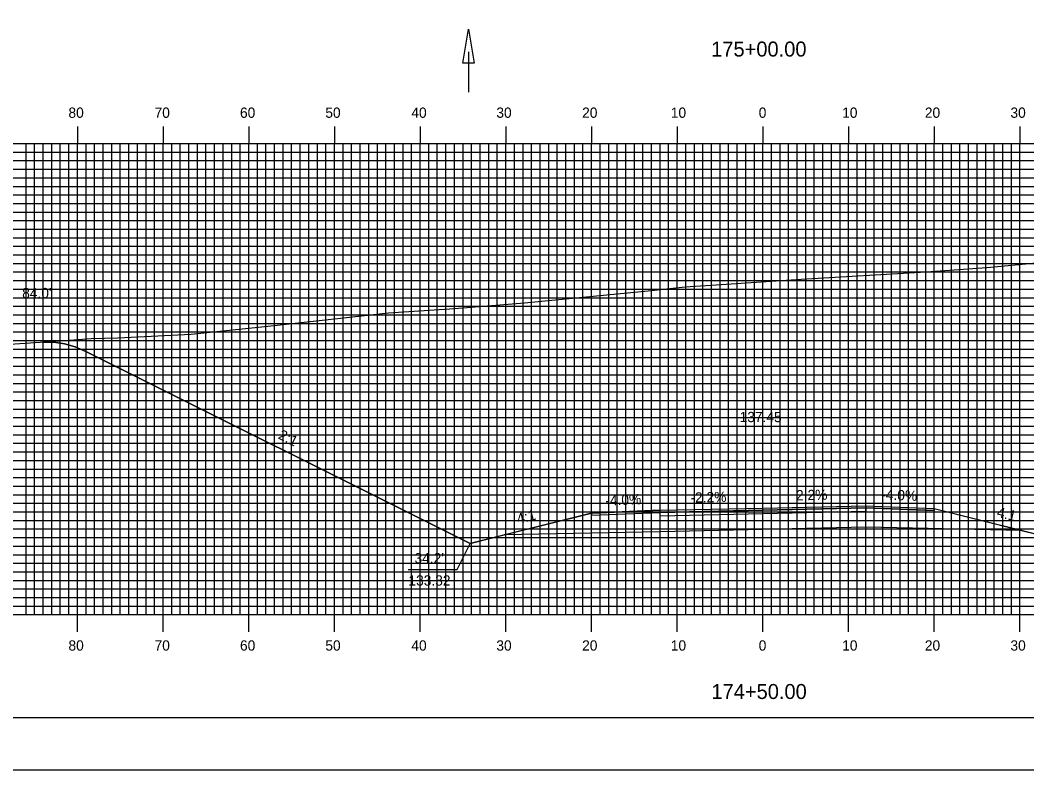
# Model space of a CAD drawing. Extents: x 1783828 to 1784171, y 442591 to 442811.
# Drawn here: x 1783906.8 to 1784024.3, y 442590.5 to 442678.1 of the extents above; entities that cross this region are included whole.
import ezdxf

# ---------------------------------------------------------------- set-up
doc = ezdxf.new("R2010")
doc.units = 0
for name, color, linetype in [('ANNOTATION', 7, 'Continuous'), ('BORDER', 7, 'Continuous'), ('D_Drainage_Ditch_Line', 7, 'Continuous'), ('D_Roadway_Centerline', 7, 'Continuous'), ('D_Roadway_Centerline_Text', 7, 'Continuous'), ('D_Roadway_Edge_Shoulder', 7, 'Continuous'), ('D_Roadway_Edge_TW', 7, 'Continuous'), ('D_Roadway_Pavement', 7, 'Continuous'), ('D_Roadway_SlopeLines', 7, 'Continuous'), ('D_Roadway_SubGrade', 7, 'Continuous'), ('D_Text_Standard', 7, 'Continuous'), ('H_V ANNOTATION', 7, 'Continuous'), ('MAJOR', 7, 'Continuous'), ('MINOR', 7, 'Continuous'), ('PLOT BOUNDARY', 7, 'Continuous'), ('S_Roadway_Centerline', 7, 'Continuous')]:
    doc.layers.add(name, color=color, linetype=linetype)

msp = doc.modelspace()

# ---------------------------------------------------------------- linework, layer by layer
at = {"layer": 'ANNOTATION'}
msp.add_lwpolyline([(1783952.09, 442613.93), (1783957.79, 442613.93), (1783959.31, 442616.98)], dxfattribs=at)
at = {"layer": 'BORDER'}
msp.add_lwpolyline([(1783843.89, 442596.67), (1784163.89, 442596.67), (1784163.89, 442806.67), (1783843.89, 442806.67)], close=True, dxfattribs=at)
at = {"layer": 'D_Drainage_Ditch_Line'}
msp.add_line((1783959.12, 442674.38), (1783959.12, 442669.68), dxfattribs=at)
msp.add_lwpolyline([(1783959.78, 442673.06), (1783958.47, 442673.06), (1783959.12, 442677)], close=True, dxfattribs=at)
at = {"layer": 'D_Roadway_Centerline'}
msp.add_lwpolyline([(1783909.48, 442640.49), (1783910.73, 442640.48), (1783911.98, 442640.3), (1783913.23, 442639.94), (1783914.48, 442639.4), (1783959.31, 442616.98), (1783963.31, 442617.98), (1783973.49, 442620.53), (1783981.49, 442620.85), (1783993.49, 442621.11), (1784005.49, 442621.38), (1784013.49, 442621.06), (1784023.66, 442618.51), (1784028.93, 442617.2), (1784105.33, 442655.4), (1784106.58, 442655.96), (1784107.83, 442656.39), (1784109.08, 442656.7), (1784110.33, 442656.87)], dxfattribs=at)
at = {"layer": 'D_Roadway_Edge_Shoulder'}
for points in [[(1783981.49, 442620.85), (1783973.49, 442620.53), (1783973.49, 442620.28), (1783981.49, 442620.6)], [(1784005.49, 442621.38), (1784013.49, 442621.06), (1784013.49, 442620.81), (1784005.49, 442621.13)]]:
    msp.add_lwpolyline(points, close=True, dxfattribs=at)
at = {"layer": 'D_Roadway_Edge_TW'}
msp.add_lwpolyline([(1783981.49, 442620.6), (1783981.49, 442620.85), (1783993.49, 442621.11), (1784005.49, 442621.38), (1784005.49, 442621.13), (1783993.49, 442620.86)], close=True, dxfattribs=at)
at = {"layer": 'D_Roadway_Pavement'}
msp.add_lwpolyline([(1783981.49, 442620.18), (1783981.49, 442620.6), (1783993.49, 442620.86), (1784005.49, 442621.13), (1784005.49, 442620.71), (1783993.49, 442620.44)], close=True, dxfattribs=at)
at = {"layer": 'D_Roadway_SlopeLines'}
for points in [[(1783959.31, 442616.98), (1783914.48, 442639.4), (1783913.23, 442639.94), (1783911.98, 442640.3), (1783910.73, 442640.48), (1783909.48, 442640.49)], [(1783973.49, 442620.53), (1783959.31, 442616.98)], [(1784013.49, 442621.06), (1784028.93, 442617.2)]]:
    msp.add_lwpolyline(points, dxfattribs=at)
at = {"layer": 'D_Roadway_SubGrade'}
msp.add_lwpolyline([(1783981.49, 442618.35), (1783963.31, 442617.98), (1783973.49, 442620.53), (1783973.49, 442620.28), (1783981.49, 442620.6), (1783993.49, 442620.86), (1784005.49, 442621.13), (1784013.49, 442620.81), (1784013.49, 442621.06), (1784023.66, 442618.51), (1784005.49, 442618.88), (1783993.49, 442618.61)], close=True, dxfattribs=at)
at = {"layer": 'MAJOR'}
for p, q in [((1783913.49, 442665.67), (1783913.49, 442663.67)), ((1783923.49, 442665.67), (1783923.49, 442663.67)), ((1783933.49, 442665.67), (1783933.49, 442663.67)), ((1783943.49, 442665.67), (1783943.49, 442663.67)), ((1783953.49, 442665.67), (1783953.49, 442663.67)), ((1783963.49, 442665.67), (1783963.49, 442663.67)), ((1783973.49, 442665.67), (1783973.49, 442663.67)), ((1783983.49, 442665.67), (1783983.49, 442663.67)), ((1783993.49, 442665.67), (1783993.49, 442663.67)), ((1784003.49, 442665.67), (1784003.49, 442663.67)), ((1784013.49, 442665.67), (1784013.49, 442663.67)), ((1784023.49, 442665.67), (1784023.49, 442663.67)), ((1783853.49, 442663.67), (1784133.49, 442663.67)), ((1783853.49, 442663.67), (1784133.49, 442663.67)), ((1783913.49, 442608.67), (1783913.49, 442663.67)), ((1783923.49, 442608.67), (1783923.49, 442663.67)), ((1783933.49, 442608.67), (1783933.49, 442663.67)), ((1783943.49, 442608.67), (1783943.49, 442663.67)), ((1783953.49, 442608.67), (1783953.49, 442663.67)), ((1783963.49, 442608.67), (1783963.49, 442663.67)), ((1783973.49, 442608.67), (1783973.49, 442663.67)), ((1783983.49, 442608.67), (1783983.49, 442663.67)), ((1783993.49, 442608.67), (1783993.49, 442663.67)), ((1784003.49, 442608.67), (1784003.49, 442663.67)), ((1784013.49, 442608.67), (1784013.49, 442663.67)), ((1784023.49, 442608.67), (1784023.49, 442663.67)), ((1783853.49, 442658.67), (1784133.49, 442658.67)), ((1783853.49, 442653.67), (1784133.49, 442653.67)), ((1783853.49, 442648.67), (1784133.49, 442648.67)), ((1783853.49, 442643.67), (1784133.49, 442643.67)), ((1783853.49, 442638.67), (1784133.49, 442638.67)), ((1783853.49, 442633.67), (1784133.49, 442633.67)), ((1783853.49, 442628.67), (1784133.49, 442628.67)), ((1783853.49, 442623.67), (1784133.49, 442623.67)), ((1783853.49, 442618.67), (1784133.49, 442618.67)), ((1783853.49, 442613.67), (1784133.49, 442613.67)), ((1783853.49, 442608.67), (1784133.49, 442608.67)), ((1783853.49, 442608.67), (1784133.49, 442608.67)), ((1783913.49, 442606.66), (1783913.49, 442608.67)), ((1783923.49, 442606.66), (1783923.49, 442608.67)), ((1783933.49, 442606.66), (1783933.49, 442608.67)), ((1783943.49, 442606.66), (1783943.49, 442608.67)), ((1783953.49, 442606.66), (1783953.49, 442608.67)), ((1783963.49, 442606.66), (1783963.49, 442608.67)), ((1783973.49, 442606.66), (1783973.49, 442608.67)), ((1783983.49, 442606.66), (1783983.49, 442608.67)), ((1783993.49, 442606.66), (1783993.49, 442608.67)), ((1784003.49, 442606.66), (1784003.49, 442608.67)), ((1784013.49, 442606.66), (1784013.49, 442608.67)), ((1784023.49, 442606.66), (1784023.49, 442608.67))]:
    msp.add_line(p, q, dxfattribs=at)
at = {"layer": 'MINOR'}
for p, q in [((1783853.49, 442662.67), (1784133.49, 442662.67)), ((1783907.49, 442608.67), (1783907.49, 442663.67)), ((1783908.49, 442608.67), (1783908.49, 442663.67)), ((1783909.49, 442608.67), (1783909.49, 442663.67)), ((1783910.49, 442608.67), (1783910.49, 442663.67)), ((1783911.49, 442608.67), (1783911.49, 442663.67)), ((1783912.49, 442608.67), (1783912.49, 442663.67)), ((1783914.49, 442608.67), (1783914.49, 442663.67)), ((1783915.49, 442608.67), (1783915.49, 442663.67)), ((1783916.49, 442608.67), (1783916.49, 442663.67)), ((1783917.49, 442608.67), (1783917.49, 442663.67)), ((1783918.49, 442608.67), (1783918.49, 442663.67)), ((1783919.49, 442608.67), (1783919.49, 442663.67)), ((1783920.49, 442608.67), (1783920.49, 442663.67)), ((1783921.49, 442608.67), (1783921.49, 442663.67)), ((1783922.49, 442608.67), (1783922.49, 442663.67)), ((1783924.49, 442608.67), (1783924.49, 442663.67)), ((1783925.49, 442608.67), (1783925.49, 442663.67)), ((1783926.49, 442608.67), (1783926.49, 442663.67)), ((1783927.49, 442608.67), (1783927.49, 442663.67)), ((1783928.49, 442608.67), (1783928.49, 442663.67)), ((1783929.49, 442608.67), (1783929.49, 442663.67)), ((1783930.49, 442608.67), (1783930.49, 442663.67)), ((1783931.49, 442608.67), (1783931.49, 442663.67)), ((1783932.49, 442608.67), (1783932.49, 442663.67)), ((1783934.49, 442608.67), (1783934.49, 442663.67)), ((1783935.49, 442608.67), (1783935.49, 442663.67)), ((1783936.49, 442608.67), (1783936.49, 442663.67)), ((1783937.49, 442608.67), (1783937.49, 442663.67)), ((1783938.49, 442608.67), (1783938.49, 442663.67)), ((1783939.49, 442608.67), (1783939.49, 442663.67)), ((1783940.49, 442608.67), (1783940.49, 442663.67)), ((1783941.49, 442608.67), (1783941.49, 442663.67)), ((1783942.49, 442608.67), (1783942.49, 442663.67)), ((1783944.49, 442608.67), (1783944.49, 442663.67)), ((1783945.49, 442608.67), (1783945.49, 442663.67)), ((1783946.49, 442608.67), (1783946.49, 442663.67)), ((1783947.49, 442608.67), (1783947.49, 442663.67)), ((1783948.49, 442608.67), (1783948.49, 442663.67)), ((1783949.49, 442608.67), (1783949.49, 442663.67)), ((1783950.49, 442608.67), (1783950.49, 442663.67)), ((1783951.49, 442608.67), (1783951.49, 442663.67)), ((1783952.49, 442608.67), (1783952.49, 442663.67)), ((1783954.49, 442608.67), (1783954.49, 442663.67)), ((1783955.49, 442608.67), (1783955.49, 442663.67)), ((1783956.49, 442608.67), (1783956.49, 442663.67)), ((1783957.49, 442608.67), (1783957.49, 442663.67)), ((1783958.49, 442608.67), (1783958.49, 442663.67)), ((1783959.49, 442608.67), (1783959.49, 442663.67)), ((1783960.49, 442608.67), (1783960.49, 442663.67)), ((1783961.49, 442608.67), (1783961.49, 442663.67)), ((1783962.49, 442608.67), (1783962.49, 442663.67)), ((1783964.49, 442608.67), (1783964.49, 442663.67)), ((1783965.49, 442608.67), (1783965.49, 442663.67)), ((1783966.49, 442608.67), (1783966.49, 442663.67)), ((1783967.49, 442608.67), (1783967.49, 442663.67)), ((1783968.49, 442608.67), (1783968.49, 442663.67)), ((1783969.49, 442608.67), (1783969.49, 442663.67)), ((1783970.49, 442608.67), (1783970.49, 442663.67)), ((1783971.49, 442608.67), (1783971.49, 442663.67)), ((1783972.49, 442608.67), (1783972.49, 442663.67)), ((1783974.49, 442608.67), (1783974.49, 442663.67)), ((1783975.49, 442608.67), (1783975.49, 442663.67)), ((1783976.49, 442608.67), (1783976.49, 442663.67)), ((1783977.49, 442608.67), (1783977.49, 442663.67)), ((1783978.49, 442608.67), (1783978.49, 442663.67)), ((1783979.49, 442608.67), (1783979.49, 442663.67)), ((1783980.49, 442608.67), (1783980.49, 442663.67)), ((1783981.49, 442608.67), (1783981.49, 442663.67)), ((1783982.49, 442608.67), (1783982.49, 442663.67)), ((1783984.49, 442608.67), (1783984.49, 442663.67)), ((1783985.49, 442608.67), (1783985.49, 442663.67)), ((1783986.49, 442608.67), (1783986.49, 442663.67)), ((1783987.49, 442608.67), (1783987.49, 442663.67)), ((1783988.49, 442608.67), (1783988.49, 442663.67)), ((1783989.49, 442608.67), (1783989.49, 442663.67)), ((1783990.49, 442608.67), (1783990.49, 442663.67)), ((1783991.49, 442608.67), (1783991.49, 442663.67)), ((1783992.49, 442608.67), (1783992.49, 442663.67)), ((1783994.49, 442608.67), (1783994.49, 442663.67)), ((1783995.49, 442608.67), (1783995.49, 442663.67)), ((1783996.49, 442608.67), (1783996.49, 442663.67)), ((1783997.49, 442608.67), (1783997.49, 442663.67)), ((1783998.49, 442608.67), (1783998.49, 442663.67)), ((1783999.49, 442608.67), (1783999.49, 442663.67)), ((1784000.49, 442608.67), (1784000.49, 442663.67)), ((1784001.49, 442608.67), (1784001.49, 442663.67)), ((1784002.49, 442608.67), (1784002.49, 442663.67)), ((1784004.49, 442608.67), (1784004.49, 442663.67)), ((1784005.49, 442608.67), (1784005.49, 442663.67)), ((1784006.49, 442608.67), (1784006.49, 442663.67)), ((1784007.49, 442608.67), (1784007.49, 442663.67)), ((1784008.49, 442608.67), (1784008.49, 442663.67)), ((1784009.49, 442608.67), (1784009.49, 442663.67)), ((1784010.49, 442608.67), (1784010.49, 442663.67)), ((1784011.49, 442608.67), (1784011.49, 442663.67)), ((1784012.49, 442608.67), (1784012.49, 442663.67)), ((1784014.49, 442608.67), (1784014.49, 442663.67)), ((1784015.49, 442608.67), (1784015.49, 442663.67)), ((1784016.49, 442608.67), (1784016.49, 442663.67)), ((1784017.49, 442608.67), (1784017.49, 442663.67)), ((1784018.49, 442608.67), (1784018.49, 442663.67)), ((1784019.49, 442608.67), (1784019.49, 442663.67)), ((1784020.49, 442608.67), (1784020.49, 442663.67)), ((1784021.49, 442608.67), (1784021.49, 442663.67)), ((1784022.49, 442608.67), (1784022.49, 442663.67)), ((1783853.49, 442661.67), (1784133.49, 442661.67)), ((1783853.49, 442660.67), (1784133.49, 442660.67)), ((1783853.49, 442659.67), (1784133.49, 442659.67)), ((1783853.49, 442657.67), (1784133.49, 442657.67)), ((1783853.49, 442656.67), (1784133.49, 442656.67)), ((1783853.49, 442655.67), (1784133.49, 442655.67)), ((1783853.49, 442654.67), (1784133.49, 442654.67)), ((1783853.49, 442652.67), (1784133.49, 442652.67)), ((1783853.49, 442651.67), (1784133.49, 442651.67)), ((1783853.49, 442650.67), (1784133.49, 442650.67)), ((1783853.49, 442649.67), (1784133.49, 442649.67)), ((1783853.49, 442647.67), (1784133.49, 442647.67)), ((1783853.49, 442646.67), (1784133.49, 442646.67)), ((1783853.49, 442645.67), (1784133.49, 442645.67)), ((1783853.49, 442644.67), (1784133.49, 442644.67)), ((1783853.49, 442642.67), (1784133.49, 442642.67)), ((1783853.49, 442641.67), (1784133.49, 442641.67)), ((1783853.49, 442640.67), (1784133.49, 442640.67)), ((1783853.49, 442639.67), (1784133.49, 442639.67)), ((1783853.49, 442637.67), (1784133.49, 442637.67)), ((1783853.49, 442636.67), (1784133.49, 442636.67)), ((1783853.49, 442635.67), (1784133.49, 442635.67)), ((1783853.49, 442634.67), (1784133.49, 442634.67)), ((1783853.49, 442632.67), (1784133.49, 442632.67)), ((1783853.49, 442631.67), (1784133.49, 442631.67)), ((1783853.49, 442630.67), (1784133.49, 442630.67)), ((1783853.49, 442629.67), (1784133.49, 442629.67)), ((1783853.49, 442627.67), (1784133.49, 442627.67)), ((1783853.49, 442626.67), (1784133.49, 442626.67)), ((1783853.49, 442625.67), (1784133.49, 442625.67)), ((1783853.49, 442624.67), (1784133.49, 442624.67)), ((1783853.49, 442622.67), (1784133.49, 442622.67)), ((1783853.49, 442621.67), (1784133.49, 442621.67)), ((1783853.49, 442620.67), (1784133.49, 442620.67)), ((1783853.49, 442619.67), (1784133.49, 442619.67)), ((1783853.49, 442617.67), (1784133.49, 442617.67)), ((1783853.49, 442616.67), (1784133.49, 442616.67)), ((1783853.49, 442615.67), (1784133.49, 442615.67)), ((1783853.49, 442614.67), (1784133.49, 442614.67)), ((1783853.49, 442612.67), (1784133.49, 442612.67)), ((1783853.49, 442611.67), (1784133.49, 442611.67)), ((1783853.49, 442610.67), (1784133.49, 442610.67)), ((1783853.49, 442609.67), (1784133.49, 442609.67))]:
    msp.add_line(p, q, dxfattribs=at)
at = {"layer": 'PLOT BOUNDARY'}
msp.add_lwpolyline([(1783827.7, 442590.55), (1784167.7, 442590.55), (1784167.7, 442810.55), (1783827.7, 442810.55)], close=True, dxfattribs=at)
at = {"layer": 'S_Roadway_Centerline'}
msp.add_lwpolyline([(1783853.49, 442636.66), (1783867.47, 442637.71), (1783867.88, 442637.74), (1783868.37, 442637.77), (1783880.33, 442638.35), (1783890.65, 442639.22), (1783893.25, 442639.41), (1783912.06, 442640.66), (1783915.08, 442640.9), (1783918.2, 442641), (1783926.75, 442641.42), (1783936.45, 442642.43), (1783949.8, 442643.89), (1783957.51, 442644.42), (1783965.65, 442645.08), (1783980.48, 442646.51), (1783984.4, 442646.92), (1783988.6, 442647.2), (1783997.96, 442647.84), (1784012.54, 442648.67), (1784019.62, 442649.19), (1784025.41, 442649.73)], dxfattribs=at)

# ---------------------------------------------------------------- texts
at = {"layer": 'ANNOTATION'}
for s, rotation, p in [('2:1', 333.4349, (1783936.83, 442629.26)), ('-4.0%', 2.2906, (1783975.12, 442621.39)), ('-2.2%', 1.2603, (1783985.05, 442621.73)), ('2.2%', 1.2603, (1783997.37, 442622)), ('-4.0%', 357.7094, (1784007.28, 442622.11)), ('4:1', 14.0362, (1783964.93, 442619.25)), ('4:1', 345.9638, (1784020.71, 442620.11))]:
    msp.add_text(s, height=1.2, rotation=rotation, dxfattribs=at).set_placement(p)
for s, p in [("34.2'", (1783952.83, 442614.66)), ('133.32', (1783952.12, 442612.06))]:
    msp.add_text(s, height=1.2, dxfattribs=at).set_placement(p)
at = {"layer": 'D_Roadway_Centerline'}
for s, p in [('C', (1783993.48, 442621.11)), ('L', (1783993.49, 442621.1))]:
    msp.add_text(s, height=0.0146, dxfattribs=at).set_placement(p)
at = {"layer": 'D_Roadway_Centerline_Text'}
msp.add_text('137.45', height=1.2, dxfattribs=at).set_placement((1783990.77, 442631.14))
at = {"layer": 'D_Text_Standard'}
msp.add_text("84.0'", height=1.2, dxfattribs=at).set_placement((1783907.04, 442645.61))
at = {"layer": 'H_V ANNOTATION'}
for s, height, p in [('175+00.00', 1.75, (1783987.45, 442673.82)), ('80', 1.2, (1783912.44, 442666.67)), ('70', 1.2, (1783922.49, 442666.67)), ('60', 1.2, (1783932.46, 442666.67)), ('50', 1.2, (1783942.42, 442666.67)), ('40', 1.2, (1783952.46, 442666.67)), ('30', 1.2, (1783962.38, 442666.67)), ('20', 1.2, (1783972.39, 442666.67)), ('10', 1.2, (1783982.74, 442666.67)), ('0', 1.2, (1783993, 442666.67)), ('10', 1.2, (1784002.74, 442666.67)), ('20', 1.2, (1784012.39, 442666.67)), ('30', 1.2, (1784022.38, 442666.67)), ('80', 1.2, (1783912.44, 442604.47)), ('70', 1.2, (1783922.49, 442604.47)), ('60', 1.2, (1783932.46, 442604.47)), ('50', 1.2, (1783942.42, 442604.47)), ('40', 1.2, (1783952.46, 442604.47)), ('30', 1.2, (1783962.38, 442604.47)), ('20', 1.2, (1783972.39, 442604.47)), ('10', 1.2, (1783982.74, 442604.47)), ('0', 1.2, (1783993, 442604.47)), ('10', 1.2, (1784002.74, 442604.47)), ('20', 1.2, (1784012.39, 442604.47)), ('30', 1.2, (1784022.38, 442604.47)), ('174+50.00', 1.75, (1783987.48, 442598.82))]:
    msp.add_text(s, height=height, dxfattribs=at).set_placement(p)

doc.saveas('drawing.dxf')
